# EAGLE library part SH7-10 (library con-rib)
RIBBON CABLE CONNECTOR Flachstecker / Faston
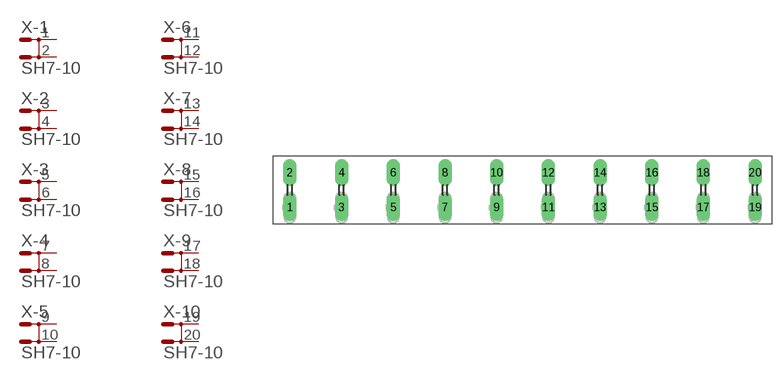
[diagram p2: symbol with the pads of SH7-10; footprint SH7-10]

Designator prefix X; gates -1=MD -2=MD -3=MD -4=MD -5=MD -6=MD -7=MD -8=MD -9=MD -10=MD

## SH7-10  [SH7-10]
1  -1:1  pas
2  -1:2  pas
3  -2:1  pas
4  -2:2  pas
5  -3:1  pas
6  -3:2  pas
7  -4:1  pas
8  -4:2  pas
9  -5:1  pas
10  -5:2  pas
11  -6:1  pas
12  -6:2  pas
13  -7:1  pas
14  -7:2  pas
15  -8:1  pas
16  -8:2  pas
17  -9:1  pas
18  -9:2  pas
19  -10:1  pas
20  -10:2  pas

## Footprint SH7-10 (pad centres in mm)
RIBBON CABLE CONNECTOR Flachstecker / Faston
drill 1.321 long: 1 -33.757,-2.515; 2 -33.757,2.515; 3 -26.238,-2.515; 4 -26.238,2.515; 5 -18.745,-2.515; 6 -18.745,2.515; 7 -11.227,-2.515; 8 -11.227,2.515; 9 -3.759,-2.515; 10 -3.759,2.515; 11 3.759,-2.515; 12 3.759,2.515; 13 11.252,-2.515; 14 11.252,2.515; 15 18.771,-2.515; 16 18.771,2.515; 17 26.238,-2.515; 18 26.238,2.515; 19 33.757,-2.515; 20 33.757,2.515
